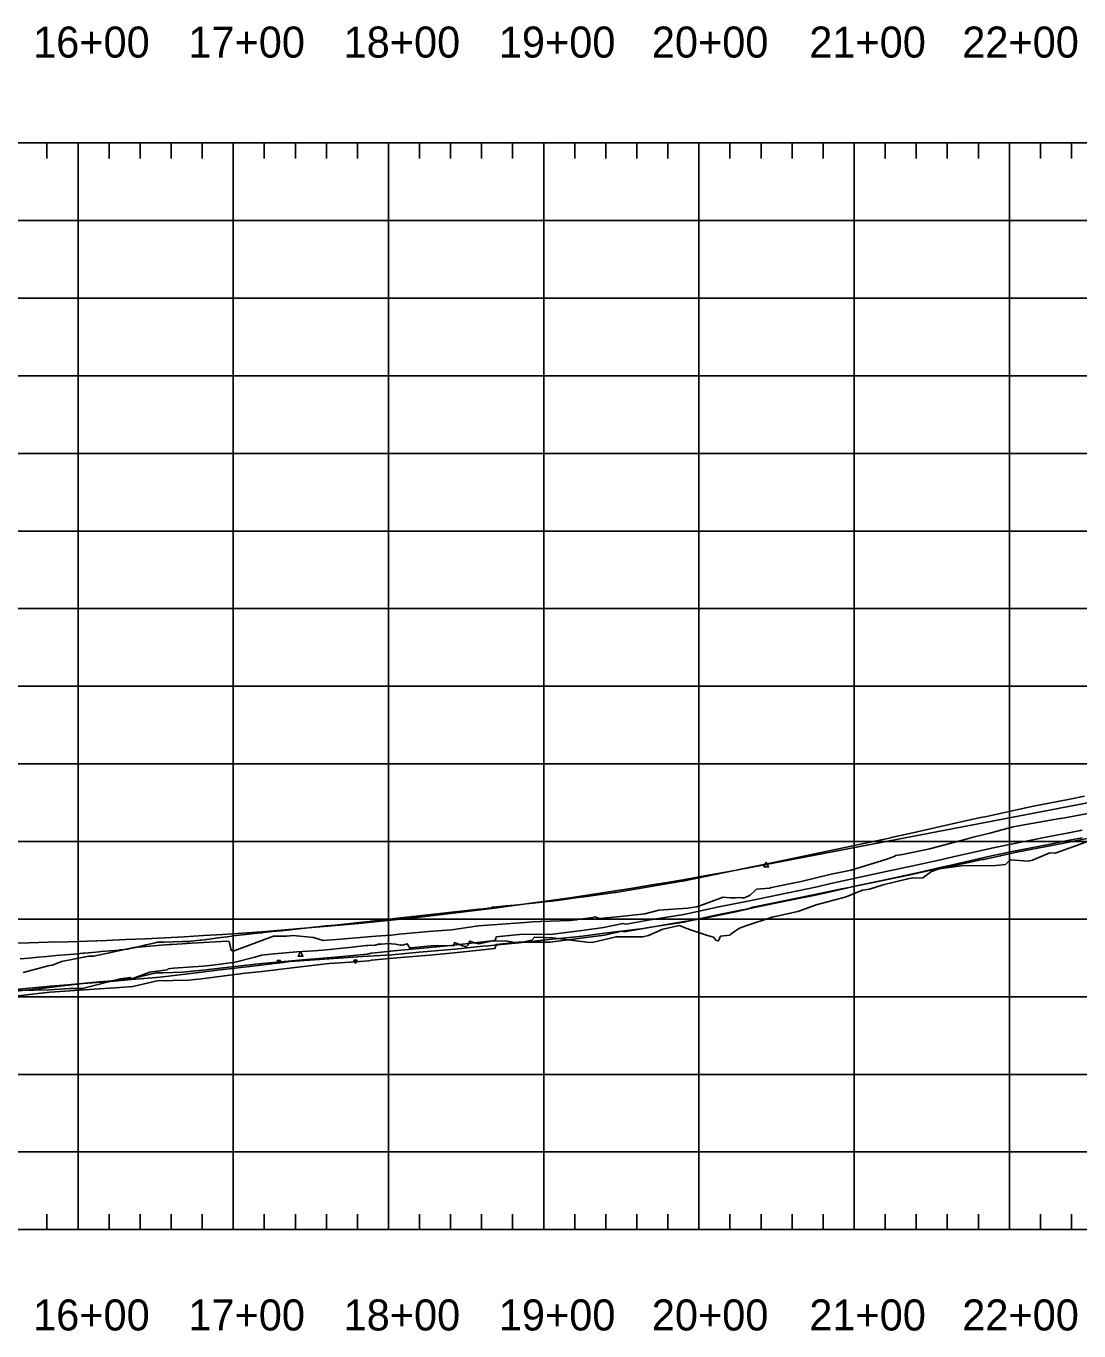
# Model space of a CAD drawing. Extents: x 704797 to 712284, y 374940 to 376945.
# Drawn here: x 708700 to 709378, y 375160 to 376001 of the extents above; entities that cross this region are included whole.
import ezdxf

# ---------------------------------------------------------------- set-up
doc = ezdxf.new("R2010")
doc.units = 0
for name, color, linetype in [('10', 7, 'Continuous'), ('12', 7, 'Continuous'), ('13', 7, 'Continuous'), ('48', 7, 'Continuous'), ('61', 7, 'Continuous'), ('Existing', 7, 'Continuous')]:
    doc.layers.add(name, color=color, linetype=linetype)

msp = doc.modelspace()

# ---------------------------------------------------------------- linework, layer by layer
for points in [[(709177.04, 375462.12), (709178.54, 375459.12), (709175.54, 375459.12)], [(708877.04, 375404.58), (708878.54, 375401.58), (708875.54, 375401.58)]]:
    msp.add_lwpolyline(points, close=True)
at = {"layer": '10'}
for points in [[(709393.54, 375495.16), (709369.47, 375490.67), (709366.81, 375490.26), (709366.1, 375490.23), (709335.81, 375484.83), (709334.72, 375484.55), (709334.33, 375484.52), (709321.11, 375480.82), (709310.39, 375478.29), (709310.38, 375478.28), (709305.75, 375476.92), (709283.92, 375471.09), (709282.32, 375470.64), (709264.9, 375467.08), (709260.62, 375466.43), (709259.54, 375465.84), (709254.8, 375464.05), (709231.69, 375457.05), (709218.97, 375454.51), (709199.47, 375449.79), (709180.52, 375445.9), (709179.12, 375445.45), (709170.84, 375444.73), (709166.75, 375440.94), (709162.97, 375439.28), (709161.22, 375439.28), (709159.61, 375439.45), (709157.25, 375439.16), (709153.72, 375439.1), (709149.2, 375439.62), (709135.89, 375434.6), (709132.03, 375433.32), (709126.32, 375432.52), (709107.84, 375431.23), (709098.8, 375428.93), (709080.98, 375426.9), (709069.63, 375425.9), (709066.71, 375426.85), (709065.54, 375426.54), (709055.47, 375425.15), (709054.86, 375425.1), (709050.83, 375424.64), (709031.41, 375423.87), (709026.58, 375423.69), (709021.45, 375423.3), (708991.62, 375421.22), (708974.2, 375418.48), (708959.48, 375417.44), (708940.68, 375415.68), (708935.43, 375415.08), (708925.51, 375414.52), (708900.25, 375412.44), (708893.89, 375411.93), (708891.54, 375411.76), (708885.34, 375413.69), (708872.3, 375415.02), (708868.06, 375414.55), (708866.38, 375414.49), (708859.59, 375414.38), (708833.69, 375404.85), (708832.29, 375405.4), (708831.03, 375410.97), (708829.33, 375411.18), (708807.14, 375410.08), (708794.18, 375409.21), (708794.05, 375409.18), (708793.94, 375409.2), (708793.49, 375409.18), (708792.55, 375409.19), (708769.64, 375407.18), (708754.79, 375404.06), (708743.65, 375401.57), (708740.72, 375401.7), (708723.01, 375398.12), (708717.32, 375395.81), (708715.31, 375395.49), (708698.44, 375391.04)], [(708695.19, 375379.52), (708715.38, 375379.96), (708728.25, 375380.8), (708736.67, 375380.83), (708760.88, 375386.95), (708767.39, 375387.91), (708767.72, 375386.86), (708779.87, 375391.35), (708791.1, 375392.78), (708791.69, 375393.38), (708795.13, 375393.8), (708807.83, 375394.7), (708814.36, 375395.1), (708820.47, 375395.9), (708834.87, 375397.66), (708847.68, 375400.87), (708851.92, 375402.15), (708859.98, 375403.01), (708874.65, 375404.43), (708885.9, 375405.02), (708891.4, 375405.5), (708908.41, 375407.21), (708919.53, 375408.5), (708920.37, 375408.46), (708925.02, 375408.74), (708927.17, 375409.26), (708929.13, 375409.32), (708934.24, 375409.74), (708935.7, 375409.55), (708938.21, 375409.4), (708941.46, 375408.79), (708941.9, 375408.84), (708942.76, 375408.76), (708945.77, 375409.65), (708946.58, 375408.31), (708947.05, 375407.36), (708947.18, 375406.91), (708948.13, 375406.99), (708960.88, 375408.34), (708972.75, 375408.44), (708975.65, 375408.26), (708975.96, 375409.57), (708976.13, 375410.39), (708980.87, 375408.55), (708983.64, 375407.63), (708984.94, 375409), (708985.16, 375409.39), (708985.84, 375411.08), (708986.28, 375411.28), (708988.98, 375410.16), (708991.83, 375409.64), (708995.89, 375410.47), (708999.8, 375411.21), (709009.21, 375411.57), (709016.73, 375410.07), (709025.97, 375411.81), (709027.75, 375413.88), (709039.43, 375413.44), (709061.38, 375410.64), (709064.95, 375410.46), (709080.27, 375414.07), (709081.66, 375414.11), (709082.32, 375413.98), (709097.46, 375414.09), (709101.25, 375414.85), (709110.39, 375418.9), (709121.17, 375421.43), (709125.31, 375419.59), (709125.33, 375419.59), (709128.26, 375418.62), (709139.14, 375414.97), (709143.1, 375413.83), (709144.89, 375411.65), (709146.32, 375411.55), (709147.48, 375414.48), (709153.62, 375415.04), (709154.28, 375415.8), (709156.56, 375417.4), (709159.85, 375419.68), (709163.95, 375421.17), (709180.92, 375426.63), (709197.42, 375430.45), (709209.8, 375434.89), (709210.01, 375434.88), (709228.59, 375439.92), (709239.06, 375444.15), (709243.52, 375444.72), (709252.35, 375447.54), (709268.18, 375451.42), (709270.5, 375451.88), (709277.83, 375452.11), (709283.43, 375456.16), (709288.54, 375457.8), (709302.59, 375459.77), (709324.91, 375460.06), (709331.08, 375460.61), (709333.45, 375463.12), (709334.43, 375463.66), (709345.85, 375462.9), (709348.62, 375463.55), (709359.79, 375468.22), (709363.25, 375467.97), (709375.15, 375472.28), (709386.33, 375476.25)]]:
    msp.add_lwpolyline(points, dxfattribs=at)
at = {"layer": '12'}
for points in [[(708693.31, 375380.02), (708716.04, 375382.23), (708727.08, 375383.15), (708747.38, 375385.03), (708758.23, 375386.03), (708769.63, 375387.34), (708784.09, 375390.77), (708788.59, 375390.92), (708800.74, 375391.19), (708814.08, 375392.52), (708840.37, 375395.63), (708852.29, 375396.79), (708859.46, 375397.56), (708878.44, 375399.17), (708899.33, 375400.99), (708920.13, 375402.95), (708922.58, 375403.53), (708925.19, 375403.81), (708934.97, 375404.72), (708960.27, 375407.08), (708973.84, 375408.45), (709002.34, 375411.62), (709002.85, 375413.26), (709003.09, 375414.11), (709018.07, 375415.62), (709030.88, 375415.68), (709037.89, 375415.64), (709058.37, 375418.17), (709072.15, 375420), (709084.6, 375422.71), (709086.71, 375422.28), (709100.92, 375424.7), (709101.08, 375424.7), (709123.98, 375428.42), (709146.5, 375433.28), (709166.36, 375437.31), (709191.11, 375442.42), (709209.95, 375446.3), (709218.71, 375448.33), (709231.59, 375451.3), (709251.35, 375455.48), (709274.38, 375460.44), (709289.22, 375463.75), (709297.43, 375465.6), (709322.31, 375471.2), (709323.27, 375471.35), (709334.86, 375473.85), (709346.72, 375476.13), (709359.32, 375478.6), (709371.86, 375481.1), (709380.57, 375482.81)], [(708693.32, 375375.9), (708708.03, 375377.45), (708715.75, 375378.36), (708747.42, 375380.46), (708757.55, 375381.12), (708768.94, 375382.1), (708784.63, 375385.62), (708805.09, 375386.13), (708813.29, 375387.03), (708813.34, 375387.04), (708841.31, 375390.62), (708852.28, 375391.78), (708873.45, 375394.23), (708895.47, 375396.87), (708908.92, 375397.71), (708920.99, 375398.58), (708922.78, 375398.97), (708939.05, 375400.42), (708960.08, 375402.28), (708976.05, 375403.82), (709002.3, 375406.64), (709002.81, 375408.26), (709003.04, 375409.09), (709017.48, 375410.57), (709037.82, 375410.58), (709057.67, 375413.12), (709072.81, 375415.23), (709084, 375417.7), (709085.79, 375417.32), (709093.02, 375418.59), (709103.85, 375420.4), (709103.98, 375420.4), (709123.89, 375423.55), (709145.51, 375428.14), (709166.35, 375432.3), (709192.38, 375437.59), (709209.81, 375441.13), (709234.22, 375446.7), (709237.19, 375447.33), (709250.73, 375450.22), (709275.37, 375455.58), (709289.07, 375458.67), (709297.13, 375460.5), (709322.13, 375466.2), (709323.12, 375466.35), (709335.53, 375469.05), (709358.78, 375473.57), (709372.3, 375476.25), (709380.62, 375477.87)]]:
    msp.add_lwpolyline(points, dxfattribs=at)
for points in [[(708863.01, 375396.86), (708862.01, 375398.86), (708864.01, 375398.86)], [(708912.44, 375396.97), (708911.44, 375398.97), (708913.44, 375398.97)]]:
    msp.add_lwpolyline(points, close=True, dxfattribs=at)
at = {"layer": '13'}
msp.add_lwpolyline([(709389.1, 375478.49), (709367.65, 375474.26), (709356.61, 375472.12), (709338.56, 375468.5), (709327.77, 375466.16), (709317.12, 375463.95), (709316.2, 375463.83), (709316.15, 375463.93), (709308.57, 375462.24), (709283.29, 375456.99), (709269.68, 375453.93), (709244.74, 375448.86), (709226.94, 375445.1), (709225.78, 375444.87), (709205.07, 375440.65), (709189.47, 375437.4), (709168.32, 375433.08), (709164.7, 375431.78), (709156.43, 375429.98), (709137.42, 375426.05), (709112.76, 375421.92), (709108.09, 375421.12), (709097.97, 375419.44), (709072.95, 375416.4), (709058.66, 375414.43), (709035.02, 375412.04), (709019.64, 375410.4), (708997.76, 375408.35), (708994.51, 375408.04), (708976.47, 375406.17), (708953.41, 375404.23), (708935.83, 375402.48), (708916.9, 375401.47), (708889.29, 375399.35), (708870.06, 375398.06), (708865.61, 375397.53), (708844.35, 375394.85), (708825.21, 375392.75), (708808.1, 375390.56), (708786.7, 375388.08), (708768.39, 375386.62), (708752.15, 375385.03), (708737.11, 375383.92), (708725.82, 375382.66), (708704.38, 375380.21), (708689.31, 375378.72)], dxfattribs=at)
at = {"layer": '48'}
msp.add_line((709177.04, 375460.62), (709500.55, 375522.67), dxfattribs=at)
msp.add_lwpolyline([(708689.54, 375410.05), (708702.04, 375410.27), (708714.54, 375410.55), (708727.04, 375410.89), (708739.54, 375411.28), (708752.04, 375411.73), (708764.54, 375412.24), (708777.04, 375412.8), (708789.54, 375413.42), (708802.04, 375414.1), (708814.54, 375414.83), (708827.04, 375415.62), (708839.54, 375416.46), (708852.04, 375417.36), (708864.54, 375418.32), (708889.54, 375420.41), (708902.04, 375421.53), (708914.54, 375422.72), (708927.04, 375423.96), (708939.54, 375425.25), (708952.04, 375426.61), (708964.54, 375428.02), (708977.04, 375429.48), (708989.54, 375431.01), (709002.04, 375432.58), (709014.54, 375434.22), (709027.04, 375435.91), (709039.54, 375437.66), (709052.04, 375439.47), (709064.54, 375441.33), (709077.04, 375443.24), (709089.54, 375445.22), (709102.04, 375447.25), (709114.54, 375449.34), (709127.04, 375451.48), (709139.54, 375453.68), (709152.04, 375455.94), (709164.54, 375458.25), (709177.04, 375460.62)], dxfattribs=at)
at = {"layer": '61'}
for p, q in [((708133.69, 375925.47), (712133.69, 375925.47)), ((708713.69, 375925.47), (708713.69, 375915.47)), ((708733.69, 375225.47), (708733.69, 375925.47)), ((708753.69, 375925.47), (708753.69, 375915.47)), ((708773.69, 375925.47), (708773.69, 375915.47)), ((708793.69, 375925.47), (708793.69, 375915.47)), ((708813.69, 375925.47), (708813.69, 375915.47)), ((708833.69, 375225.47), (708833.69, 375925.47)), ((708853.69, 375925.47), (708853.69, 375915.47)), ((708873.69, 375925.47), (708873.69, 375915.47)), ((708893.69, 375925.47), (708893.69, 375915.47)), ((708913.69, 375925.47), (708913.69, 375915.47)), ((708933.69, 375225.47), (708933.69, 375925.47)), ((708953.69, 375925.47), (708953.69, 375915.47)), ((708973.69, 375925.47), (708973.69, 375915.47)), ((708993.69, 375925.47), (708993.69, 375915.47)), ((709013.69, 375925.47), (709013.69, 375915.47)), ((709033.69, 375225.47), (709033.69, 375925.47)), ((709053.69, 375925.47), (709053.69, 375915.47)), ((709073.69, 375925.47), (709073.69, 375915.47)), ((709093.69, 375925.47), (709093.69, 375915.47)), ((709113.69, 375925.47), (709113.69, 375915.47)), ((709133.69, 375225.47), (709133.69, 375925.47)), ((709153.69, 375925.47), (709153.69, 375915.47)), ((709173.69, 375925.47), (709173.69, 375915.47)), ((709193.69, 375925.47), (709193.69, 375915.47)), ((709213.69, 375925.47), (709213.69, 375915.47)), ((709233.69, 375225.47), (709233.69, 375925.47)), ((709253.69, 375925.47), (709253.69, 375915.47)), ((709273.69, 375925.47), (709273.69, 375915.47)), ((709293.69, 375925.47), (709293.69, 375915.47)), ((709313.69, 375925.47), (709313.69, 375915.47)), ((709333.69, 375225.47), (709333.69, 375925.47)), ((709353.69, 375925.47), (709353.69, 375915.47)), ((709373.69, 375925.47), (709373.69, 375915.47)), ((708133.69, 375875.47), (712133.69, 375875.47)), ((708133.69, 375825.47), (712133.69, 375825.47)), ((708133.69, 375775.47), (712133.69, 375775.47)), ((708133.69, 375725.47), (712133.69, 375725.47)), ((708133.69, 375675.47), (712133.69, 375675.47)), ((708133.69, 375625.47), (712133.69, 375625.47)), ((708133.69, 375575.47), (712133.69, 375575.47)), ((708133.69, 375525.47), (712133.69, 375525.47)), ((708133.69, 375475.47), (712133.69, 375475.47)), ((708133.69, 375425.47), (712133.69, 375425.47)), ((708133.69, 375375.47), (712133.69, 375375.47)), ((708133.69, 375325.47), (712133.69, 375325.47)), ((708133.69, 375275.47), (712133.69, 375275.47)), ((708713.69, 375225.47), (708713.69, 375235.47)), ((708753.69, 375225.47), (708753.69, 375235.47)), ((708773.69, 375225.47), (708773.69, 375235.47)), ((708793.69, 375225.47), (708793.69, 375235.47)), ((708813.69, 375225.47), (708813.69, 375235.47)), ((708853.69, 375225.47), (708853.69, 375235.47)), ((708873.69, 375225.47), (708873.69, 375235.47)), ((708893.69, 375225.47), (708893.69, 375235.47)), ((708913.69, 375225.47), (708913.69, 375235.47)), ((708953.69, 375225.47), (708953.69, 375235.47)), ((708973.69, 375225.47), (708973.69, 375235.47)), ((708993.69, 375225.47), (708993.69, 375235.47)), ((709013.69, 375225.47), (709013.69, 375235.47)), ((709053.69, 375225.47), (709053.69, 375235.47)), ((709073.69, 375225.47), (709073.69, 375235.47)), ((709093.69, 375225.47), (709093.69, 375235.47)), ((709113.69, 375225.47), (709113.69, 375235.47)), ((709153.69, 375225.47), (709153.69, 375235.47)), ((709173.69, 375225.47), (709173.69, 375235.47)), ((709193.69, 375225.47), (709193.69, 375235.47)), ((709213.69, 375225.47), (709213.69, 375235.47)), ((709253.69, 375225.47), (709253.69, 375235.47)), ((709273.69, 375225.47), (709273.69, 375235.47)), ((709293.69, 375225.47), (709293.69, 375235.47)), ((709313.69, 375225.47), (709313.69, 375235.47)), ((709353.69, 375225.47), (709353.69, 375235.47)), ((709373.69, 375225.47), (709373.69, 375235.47)), ((708133.69, 375225.47), (712133.69, 375225.47))]:
    msp.add_line(p, q, dxfattribs=at)
at = {"layer": 'Existing'}
msp.add_lwpolyline([(708696.36, 375399.8), (708702.16, 375400.36), (708707.95, 375400.9), (708713.75, 375401.43), (708719.55, 375401.96), (708725.34, 375402.47), (708731.14, 375402.98), (708736.94, 375403.48), (708737.59, 375403.54), (708742.73, 375404.01), (708747.31, 375404.43), (708748.53, 375404.54), (708754.33, 375405.06), (708760.12, 375405.57), (708760.88, 375405.64), (708765.92, 375406.18), (708766.3, 375406.22), (708771.72, 375407.48), (708777.52, 375408.83), (708783.31, 375410.17), (708784.93, 375410.54), (708789.11, 375410.66), (708794.91, 375410.83), (708800.7, 375410.99), (708805.71, 375411.13), (708806.5, 375411.22), (708812.3, 375411.89), (708813.23, 375411.99), (708818.09, 375412.63), (708823.89, 375413.39), (708829.69, 375414.13), (708835.48, 375414.86), (708841.28, 375415.58), (708841.55, 375415.62), (708847.08, 375416.18), (708852.11, 375416.69), (708852.87, 375416.77), (708858.67, 375417.4), (708864.47, 375418.01), (708870.26, 375418.62), (708875.79, 375419.2), (708876.06, 375419.23), (708881.86, 375419.84), (708887.65, 375420.45), (708893.45, 375421.04), (708899.25, 375421.63), (708905.04, 375422.21), (708907.43, 375422.44), (708910.84, 375422.8), (708916.64, 375423.4), (708921.41, 375423.89), (708922.43, 375424.13), (708922.9, 375424.25), (708928.23, 375424.85), (708934.03, 375425.5), (708939.82, 375426.14), (708945.62, 375426.78), (708949.15, 375427.16), (708951.42, 375427.41), (708957.21, 375428.03), (708959.2, 375428.24), (708963.01, 375428.68), (708968.81, 375429.33), (708974.6, 375429.98), (708980.4, 375430.62), (708986.2, 375431.26), (708991.99, 375431.89), (708996.9, 375432.41), (708997.79, 375432.52), (709000.17, 375432.79), (709000.22, 375432.97), (709000.25, 375433.06), (709003.59, 375433.4), (709009.38, 375433.98), (709015.18, 375434.56), (709020.98, 375435.15), (709022.3, 375435.28), (709026.77, 375435.76), (709032.57, 375436.37), (709038.37, 375436.98), (709039.37, 375437.09), (709040.39, 375437.19), (709044.16, 375437.71), (709049.96, 375438.5), (709055.76, 375439.3), (709061.55, 375440.1), (709067.35, 375440.89), (709079.61, 375442.58), (709080.2, 375442.66), (709122.67, 375449.9), (709123.37, 375450.02), (709169.02, 375459.38), (709169.05, 375459.39), (709169.07, 375459.39), (709169.16, 375459.41), (709211.41, 375468.17), (709257.31, 375477.92), (709257.52, 375477.96), (709269.5, 375480.67), (709293.98, 375486.16), (709315.06, 375490.93), (709315.29, 375490.99), (709316.35, 375491.15), (709317.87, 375491.36), (709318, 375491.38), (709341.22, 375496.46), (709349.16, 375498.18), (709349.27, 375498.2), (709371.62, 375502.59), (709382.14, 375504.65)], dxfattribs=at)

# ---------------------------------------------------------------- texts
at = {"layer": '61'}
for s, p in [('16+00', (708704.77, 375980.47)), ('17+00', (708804.77, 375980.47)), ('18+00', (708904.77, 375980.47)), ('19+00', (709004.77, 375980.47)), ('20+00', (709103.32, 375980.47)), ('21+00', (709204.77, 375980.47)), ('22+00', (709303.32, 375980.47)), ('16+00', (708704.77, 375160.47)), ('17+00', (708804.77, 375160.47)), ('18+00', (708904.77, 375160.47)), ('19+00', (709004.77, 375160.47)), ('20+00', (709103.32, 375160.47)), ('21+00', (709204.77, 375160.47)), ('22+00', (709303.32, 375160.47))]:
    msp.add_text(s, height=20, dxfattribs=at).set_placement(p)

doc.saveas('drawing.dxf')
